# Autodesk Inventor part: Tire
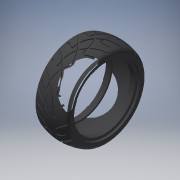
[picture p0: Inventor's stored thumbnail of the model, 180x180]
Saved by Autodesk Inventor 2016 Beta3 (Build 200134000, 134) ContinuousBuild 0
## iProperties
Shininess: 25.0
Length Units: 11272
Angle Units: 11279
Time Units: 11290
Mass Units: 11286
Length Display Precision: 4
Angle Display Precision: 2
Compacted: True
Company: Autodesk
Created: 2000-05
Part Number: Tire
Project: Inventor Samples
User Status: IN PROGRESS
Document SubType Name: Modeling
Designer: Autodesk, Inc.
Density: 0.93 g/cm^3
Material: Rubber
Mass: 9.0169 g
Surface Area: 189.656 cm^2
Volume: 9.69559 cm^3
Appearance: Black
Density: 0.0
Volumn: 0.0
Area: 0.0
PropertySet Name: Model Information
Control State: 0
Master: False
Checked Out: False
Last Check In By: Kevin.s
Last Check In Date: 2002-03-02
Author: Autodesk, Inc.
Revision Number: A
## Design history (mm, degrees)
node "Revolution1" dims "d7" = 90 deg
  sketch "Sketch2"
    geometry: L1 (-10.926, 4.597)-(-14.99, 4.597); L2 (-14.99, 4.597)-(-14.99, 6.629); L3 (-14.99, 6.629)-(-16.768, 6.629); L4 (-16.768, 6.629)-(-16.768, 10.893); L5 (-19.353, -19.342)-(12.36, -19.342) reference; L6 (9.775, 10.893)-(9.775, 6.629); L7 (9.775, 6.629)-(7.997, 6.629); L8 (7.997, 6.629)-(7.997, 4.597); L9 (7.997, 4.597)-(3.933, 4.597); L10 (-10.926, 5.867)-(-13.72, 5.867); L11 (-13.72, 5.867)-(-13.72, 7.899); L12 (-13.72, 7.899)-(-15.498, 7.899); L13 (-15.498, 7.899)-(-15.498, 10.052); L14 (8.505, 10.052)-(8.505, 7.899); L15 (8.505, 7.899)-(6.727, 7.899); L16 (6.727, 7.899)-(6.727, 5.867); L17 (6.727, 5.867)-(3.933, 5.867); L18 (-10.926, 4.597)-(-10.926, 5.867); L19 (3.933, 4.597)-(3.933, 5.867); A1 r 33.02 centre (-3.496, -19.342) between (9.775, 10.893) and (-16.768, 10.893); A2 r 31.75 centre (-3.496, -19.342) between (8.505, 10.052) and (-15.498, 10.052)
    constraints: 38 end point, 9 parallel, 7 perpendicular, 4 collinear, 4 equal length, 4 point on circle, 2 centre point, 2 horizontal, 2 midpoint, 1 horizontal alignment, 9 other
    dimensions: "d0" = 47.879 diameter of L1 L5; "d1" = 51.943 diameter of L3 L5; "d2" = 1.778 distance of L2.end L3.end; "d3" = 5.842 distance from line of L4 L1.start; "d4" = 26.543 distance between parallel lines of L6 L4; "d5" = 66.04 dimension on A1 L5; "d6" = 1.27 radial gap between concentric circles of A1 A2
workaxis "Work Axis1"
node "Fillet1" dims "d8" = 3.175
sketch "Sketch7"
  geometry: L1 (-46.46, -19.342)-(23.146, -19.342) reference; A1 r 33.02 centre (-3.496, -19.342) between (7.674, 11.731) and (7.674, -50.415) reference; A2 r 32.266 centre (-3.496, -19.342) between (13.202, 8.266) and (-20.195, 8.266)
  constraints: 2 point on circle, 1 centre point, 1 coincident
feature "RevolutionSrf1" sketch "Sketch7" dims angle "d63" = 90 deg
workplane "Work Plane6"
sketch "Sketch8"
  geometry: L1 (-9.775, -14.127)-(-9.775, -13.038); L2 (-9.775, -28.085)-(-9.775, 28.085) reference; L3 (7.675, 6.132)-(7.941, 8.812); L4 (8.727, 9.228)-(13.347, 6.713); L5 (13.851, 7.638)-(9.231, 10.154); L6 (8.15, 14.674)-(8.152, 14.673); L7 (6.892, 8.916)-(6.626, 6.236); L8 (23.217, 0)-(-21.924, 0) reference; L9 (16.768, 28.085)-(16.768, -28.085) reference; A1 r 23.264 centre (-15.476, 8.428) between (-9.775, -14.127) and (7.685, 6.236); A2 r 22.21 centre (-15.476, 8.428) between (-9.775, -13.038) and (6.626, 6.236); A3 r 0.533 centre (8.472, 8.76) between (8.727, 9.228) and (7.941, 8.812); A4 r 0.527 centre (13.599, 7.175) between (13.347, 6.713) and (13.851, 7.638); A5 r 1.587 centre (8.472, 8.76) between (9.231, 10.154) and (6.892, 8.916)
  constraints: 12 end point, 11 point on circle, 6 tangent, 5 centre point, 3 parallel, 2 concentric, 1 collinear, 1 horizontal alignment
  dimensions: "d72" = 1.0541 radial gap between concentric circles of A1 A2; "d76" = 0.52705 radius of A4 (= 0.5 x d72); "d77" = 14.12735 distance from line of L1.start L8; "d78" = 1.5875 radius of A5; "d79" = 7.1755 distance from line of L8 A4.centre; "d80" = 3.16916 distance from line of L9 A4.centre
extrude "Extrusion1" cut sketch "Sketch8" stored distance "d65" = 25.4; taper "d66" = 0 deg
pattern_circular "Circular Pattern5" dims angle "d70" = 360 deg
workplane "Work Plane7"
mirror "Mirror4"
body "Solid1"
body "Srf1"
other parameters: "d64" = 18.796, "d71" = -13.2715 (= -0.5 x d4)
